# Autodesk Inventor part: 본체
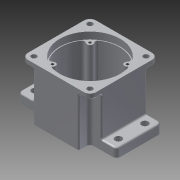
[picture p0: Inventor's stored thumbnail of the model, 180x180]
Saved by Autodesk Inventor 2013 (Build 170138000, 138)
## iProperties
Created: 2015-07
Part Number: 본체
Material: 알루미늄 6061
Document SubType Name: Modeling
Designer: user
Density: 1 g/cm^3
Author: user
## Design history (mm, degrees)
sketch "스케치1"
  geometry: L1 (-65, 30)-(65, 30); L2 (65, 30)-(65, -30); L3 (65, -30)-(-65, -30); L4 (-65, -30)-(-65, 30); L5 (-45, 45)-(45, 45); L6 (45, 45)-(45, -45); L7 (45, -45)-(-45, -45); L8 (-45, -45)-(-45, 45); 5 further points
  constraints: 16 end point, 4 midpoint, 4 parallel, 2 horizontal, 2 horizontal alignment, 2 perpendicular, 2 vertical alignment
  dimensions: "d0" = 130 distance of L2.end L3.end; "d1" = 60 distance of L1.end L2.end; "d2" = 90 distance of L6.end L7.end; "d3" = 90 distance of L5.end L6.end
extrude "돌출1" new body sketch "스케치1" distance "d4" = 12; taper "d5" = 0 deg
extrude "돌출2" join sketch "스케치1" distance "d6" = 70; taper "d7" = 0 deg
sketch "스케치2"
  geometry: L1 (-45, -45)-(45, -45) reference; L2 (65, -30)-(65, 30) reference; L3 (65, 30)-(45, 30) reference; L4 (45, 30)-(45, 45) reference; L5 (45, 45)-(-45, 45) reference; L6 (-45, 45)-(-45, 30) reference; L7 (45, 45)-(30, 45); L8 (30, 45)-(30, 30); L9 (30, 30)-(45, 30); L10 (45, 30)-(45, 45); L11 (45, -45)-(45, -30); L12 (30, -45)-(45, -45); L13 (45, -30)-(30, -30); L14 (30, -30)-(30, -45); L15 (-30, -30)-(-45, -30); L16 (-30, -45)-(-30, -30); L17 (-45, -30)-(-45, -45); L18 (-45, -45)-(-30, -45); L19 (-30, 45)-(-45, 45); L20 (-30, 30)-(-30, 45); L21 (-45, 30)-(-30, 30); L22 (-45, 45)-(-45, 30); 1 further point
  constraints: 32 end point, 6 parallel, 5 collinear, 3 perpendicular, 1 point on line
  dimensions: "d8" = 15 distance of L4.end L7.end; "d9" = 15 distance of L7.end L8.end; "d10" = 15 distance of L8.end L3.end (derived); "d11" = 15 distance of L11.end L13.end; "d12" = 15 distance of L13.end L12.start; "d13" = 15 distance of L12.start L11.start (derived); "d14" = 15 distance of L15.start L15.end; "d15" = 15 distance of L15.end L17.end; "d16" = 15 distance of L17.end L16.start (derived); "d17" = 15 distance of L19.start L19.end; "d18" = 15 distance of L19.end L21.start; "d19" = 15 distance of L21.start L20.start (derived); "d20" = 60 distance between parallel lines of L3 L13; "d21" = 20 distance between parallel lines of L2 L11; "d22" = 0 distance between parallel lines of L5 L19; "d23" = 75 distance between parallel lines of L5 L15; "d24" = 15 distance between parallel lines of L6 L16; "d25" = 95 distance between parallel lines of L20 L2
extrude "돌출3" cut sketch "스케치2" distance "d26" = 63; taper "d27" = 0 deg
sketch "스케치3"
  geometry: C1 r 40 at (0, 0); 1 further point
  constraints: 1 centre point, 1 coincident
  dimensions: "d28" = 80 diameter of C1
extrude "돌출4" cut sketch "스케치3" distance "d29" = 9; taper "d30" = 0 deg
sketch "스케치4"
  geometry: C1 r 40 at (0, 0) reference; C2 r 39 at (0, 0)
  constraints: 1 centre point, 1 coincident
  dimensions: "d31" = 78 diameter of C2
extrude "돌출5" cut sketch "스케치4" distance "d32" = 52; taper "d33" = 0 deg
node "작업 평면1"
sketch "스케치5"
  geometry: L1 (30, -30)-(30, -45) reference; L2 (30, -45)-(-30, -45) reference; L3 (-30, -45)-(-30, -30) reference; L4 (-30, -30)-(-65, -30) reference; L5 (-65, -30)-(-65, 30) reference; L6 (-65, 30)-(-30, 30) reference; L7 (-30, 30)-(-30, 45) reference; L8 (-30, 45)-(30, 45) reference; L9 (30, 45)-(30, 30) reference; L10 (30, 30)-(65, 30) reference; L11 (65, 30)-(65, -30) reference; L12 (65, -30)-(30, -30) reference; L13 (45, 45)-(30, 45) reference; L14 (45, 30)-(45, 45) reference; L15 (30, 30)-(45, 30) reference; L16 (30, 45)-(30, 30) reference; L17 (-45, 45)-(-45, 30) reference; L18 (-30, 45)-(-45, 45) reference; L19 (-30, 30)-(-30, 45) reference; L20 (-45, 30)-(-30, 30) reference; L21 (-45, -45)-(-30, -45) reference; L22 (-45, -30)-(-45, -45) reference; L23 (-30, -30)-(-45, -30) reference; L24 (-30, -45)-(-30, -30) reference; L25 (45, -30)-(30, -30) reference; L26 (45, -45)-(45, -30) reference; L27 (30, -45)-(45, -45) reference; L28 (30, -30)-(30, -45) reference; L29 (0, 0)-(0, 11); C1 r 25 at (0, 11)
  constraints: 2 end point, 1 centre point, 1 coincident, 1 parallel
  dimensions: "d35" = 11 distance of L29.start L29.end; "d36" = 50 diameter of C1
extrude "돌출6" join sketch "스케치5" stored distance "d37" = 8; taper "d38" = 0 deg
sketch "스케치6"
  geometry: C1 r 25 at (0, 0) reference; C2 r 20.5 at (0, 0); 1 further point
  constraints: 1 centre point, 1 coincident
  dimensions: "d39" = 20.5 radius of C2
extrude "돌출7" join sketch "스케치6" distance "d40" = 23; taper "d41" = 0 deg
sketch "스케치7"
  geometry: L1 (-65, -30)-(-30, -30) reference; L2 (0, 0)-(0, -20); C1 r 14 at (0, -20)
  constraints: 2 end point, 1 centre point, 1 coincident, 1 perpendicular
  dimensions: "d42" = 20 distance of L2.start L2.end; "d43" = 14 radius of C1
extrude "돌출8" join sketch "스케치7" distance "d44" = 16; taper "d45" = 0 deg
sketch "스케치8"
  geometry: C1 r 17.5 at (0, 0); A1 r 20.5 centre (0, 0) between (7.402, -19.117) and (-7.402, -19.117) reference; 1 further point
  constraints: 1 centre point, 1 coincident
  dimensions: "d46" = 35 diameter of C1
extrude "돌출9" cut sketch "스케치8" distance "d47" = 10; taper "d48" = 0 deg
sketch "스케치9"
  geometry: C1 r 17.5 at (0, 0) reference; C2 r 12.5 at (0, 0); 1 further point
  constraints: 1 centre point, 1 coincident
  dimensions: "d49" = 25 diameter of C2
extrude "돌출10" cut sketch "스케치9" distance "d50" = 5; taper "d51" = 0 deg
sketch "스케치10"
  geometry: C1 r 12.5 at (0, 0) reference; C2 r 16 at (0, 0); 1 further point
  constraints: 1 centre point, 1 coincident
  dimensions: "d52" = 32 diameter of C2
extrude "돌출11" cut sketch "스케치10" distance "d53" = 8; taper "d54" = 0 deg
sketch "스케치11"
  geometry: C1 r 11 at (0, -31); A1 r 14 centre (0, -31) between (-7.402, -19.117) and (7.402, -19.117) reference; 1 further point
  constraints: 1 centre point, 1 coincident
  dimensions: "d55" = 22 diameter of C1
extrude "돌출12" cut sketch "스케치11" distance "d56" = 7; taper "d57" = 0 deg
sketch "스케치12"
  geometry: C1 r 11 at (0, 0) reference; C2 r 9.5 at (0, 0); 1 further point
  constraints: 1 centre point, 1 coincident
  dimensions: "d58" = 19 diameter of C2
extrude "돌출13" cut sketch "스케치12" distance "d59" = 1; taper "d60" = 0 deg
fillet "모깎기1" dims "d61" = 0.3
fillet "모깎기2" dims "d62" = 2
fillet "모깎기3" dims "d63" = 5
fillet "모깎기4" dims "d64" = 8
fillet "모깎기5" dims "d65" = 5
sketch "스케치13"
  geometry: L1 (0, 0)-(35, 0); L2 (0, 0)-(24.749, 24.749); L3 (28.284, 28.284)-(31.726, 31.726); A1 r 39 centre (0, 0) between (21.134, 32.777) and (32.777, 21.134) reference; A2 r 4 centre (24.749, 24.749) between (21.809, 27.462) and (27.462, 21.809); A3 r 3.5 centre (19.238, 29.836) between (21.809, 27.462) and (21.134, 32.777); A4 r 3.5 centre (29.836, 19.238) between (32.777, 21.134) and (27.462, 21.809); 1 further point
  constraints: 8 point on circle, 6 end point, 5 tangent, 3 centre point, 2 coincident, 1 collinear, 1 horizontal, 2 other
  dimensions: "d69" = 4 radius of A2; "d70" = 3.5 radius of A3; "d71" = 45 deg angle of L1 L2; "d72" = 3.5 radius of A4; "d73" = 0 distance between parallel lines of L2 L3; "d74" = 44.86791 distance of point (0, 0) L3.end
extrude "돌출14" join sketch "스케치13" stored distance "d75" = 1; taper "d76" = 0 deg
sketch "스케치14"
  geometry: A1 r 4 centre (24.749, 24.749) between (21.809, 27.462) and (27.462, 21.809) reference; A2 r 4 centre (24.749, -24.749) between (27.462, -21.809) and (21.809, -27.462) reference; A3 r 4 centre (-24.749, -24.749) between (-21.809, -27.462) and (-27.462, -21.809) reference; A4 r 4 centre (-24.749, 24.749) between (-27.462, 21.809) and (-21.809, 27.462) reference
hole "구멍1" sketch "스케치14" at (-24.749, 24.749), (-24.749, -24.749), (24.749, -24.749), (24.749, 24.749) diameter "d80" = 3.459; stored, may be unused: countersink angle "d84" = 90 deg, drill point angle "d86" = 118 deg; dims "d81" = 12, "d82" = 4, "d83" = 2, "d85" = 15
sketch "스케치15"
  geometry: L1 (-37, 37)-(37, 37); L2 (37, 37)-(37, -37); L3 (37, -37)-(-37, -37); L4 (-37, -37)-(-37, 37); C1 r 40 at (0, 0) reference; A1 r 8 centre (37, -37) between (37, -45) and (45, -37) reference; A2 r 8 centre (-37, 37) between (-37, 45) and (-45, 37) reference; A3 r 8 centre (-37, -37) between (-45, -37) and (-37, -45) reference; 2 further points
  constraints: 8 end point, 2 midpoint, 2 parallel, 1 horizontal, 1 horizontal alignment, 1 perpendicular, 1 vertical alignment
  dimensions: "d87" = 74 distance of L2.end L3.end; "d88" = 74 distance of L3.end L1.start
hole "구멍2" sketch "스케치15" at (-37, 37), (37, 37), (37, -37), (-37, -37) diameter "d89" = 7; stored, may be unused: countersink angle "d93" = 90 deg, drill point angle "d95" = 118 deg; dims "d90" = 12, "d91" = 4, "d92" = 2, "d94" = 7
sketch "스케치16"
  geometry: L1 (-55, 17.5)-(55, 17.5); L2 (55, 17.5)-(55, -17.5); L3 (55, -17.5)-(-55, -17.5); L4 (-55, -17.5)-(-55, 17.5); 3 further points
  constraints: 8 end point, 2 midpoint, 2 parallel, 1 horizontal, 1 horizontal alignment, 1 perpendicular, 1 vertical alignment
  dimensions: "d96" = 110 distance of L2.end L3.end; "d97" = 35 distance of L1.end L2.end
hole "구멍3" sketch "스케치16" at (-55, 17.5), (-55, -17.5), (55, 17.5), (55, -17.5) diameter "d98" = 9; stored, may be unused: countersink angle "d102" = 90 deg, drill point angle "d104" = 118 deg; dims "d99" = 12, "d100" = 4, "d101" = 2, "d103" = 7
fillet "모깎기7" dims "d106" = 3
fillet "모깎기8" dims "d107" = 2
chamfer "모따기1" distance "d109" = 1; stored, may be unused: second distance "d110" = 2, angle "d111" = 45 deg
sketch "스케치17"
  geometry: L1 (-30, -45)-(30, -45) reference; 4 further points
  constraints: 1 vertical alignment, 1 other
  dimensions: "d112" = 15 distance from line of L1 point (0, -30)
feature "엠보싱1" sketch "스케치17" dims "d113" = 0.5, "d114" = 0
fillet "모깎기13" dims "d118" = 2
fillet "모깎기16" dims "d121" = 2
fillet "모깎기17" dims "d122" = 2
node "솔리드1"
pattern_circular "원형 패턴1" dims angle "d78" = 360 deg
node "투영된 루프1"
node "투영된 루프2"
node "투영된 루프3"
node "투영된 루프4"
node "투영된 루프5"
other parameters: "d34" = -7, "d67" = 45 deg
